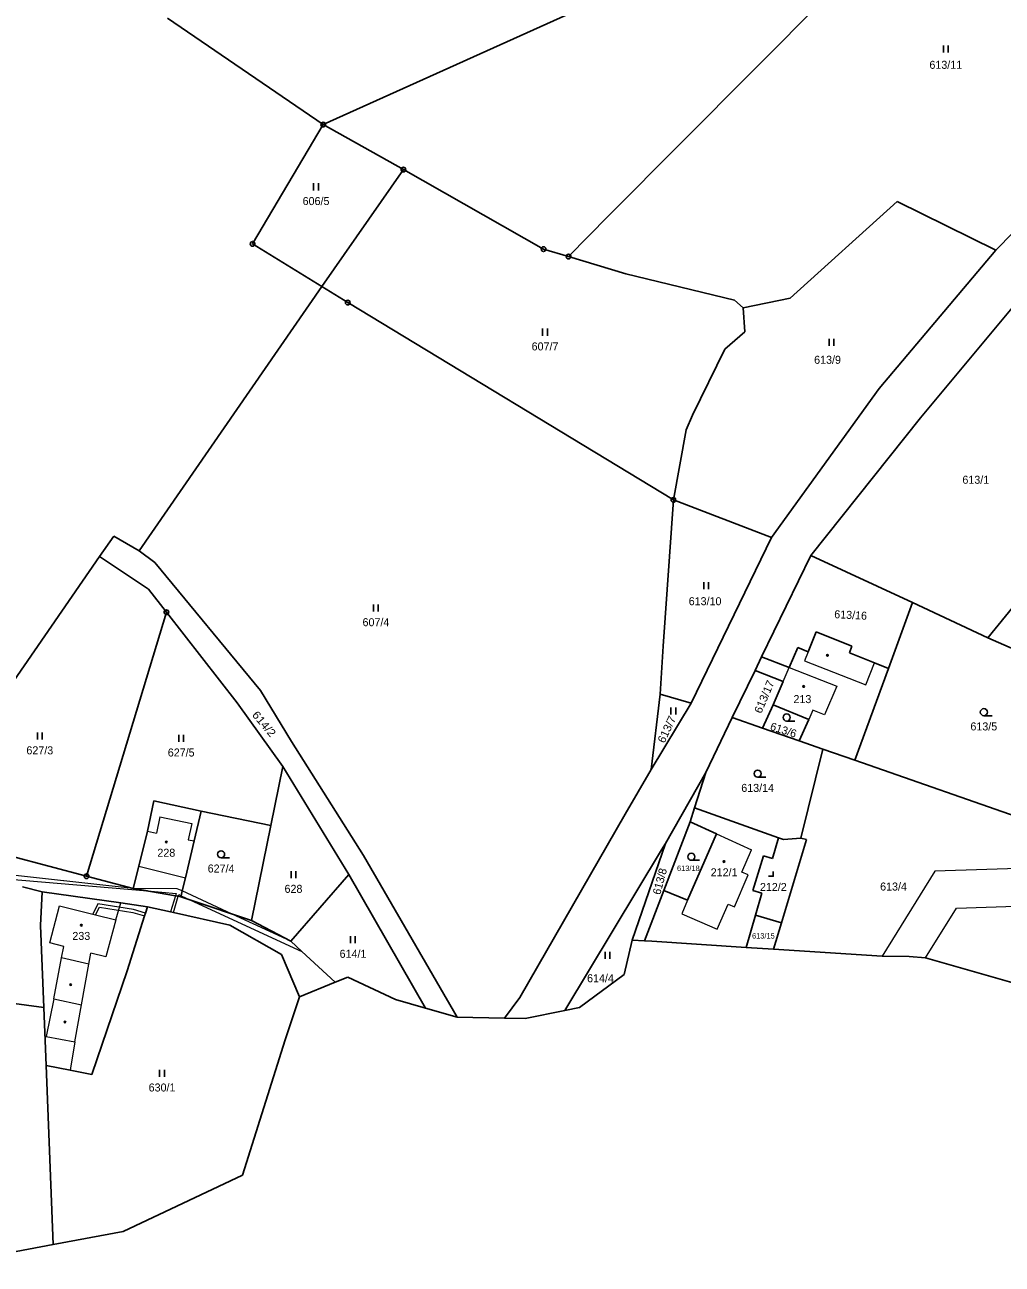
# Model space of a CAD drawing. Extents: x -739410 to -735662, y -942282 to -940043.
# Drawn here: x -737806.2 to -737598.7, y -942258.7 to -941995.4 of the extents above; entities that cross this region are included whole.
import ezdxf
from ezdxf.enums import TextEntityAlignment as Align

# ---------------------------------------------------------------- set-up
doc = ezdxf.new("R2010")
doc.units = 0
doc.header["$LTSCALE"] = 0.68
for name, color, linetype, lineweight in [('1', 7, 'Continuous', 25), ('13', 7, 'Continuous', 13), ('3', 7, 'Continuous', 25), ('4', 7, 'Continuous', 13), ('5', 7, 'Continuous', 25), ('8', 7, 'Continuous', 25)]:
    doc.layers.add(name, color=color, linetype=linetype, lineweight=lineweight)
doc.layers.add('2', color=7, linetype='Continuous')

msp = doc.modelspace()

# ---------------------------------------------------------------- linework, layer by layer
at = {"layer": '1'}
for p, q in [((-737682.23, -942036.04), (-737602.58, -941955.83)), ((-737742.81, -942016.64), (-737660.83, -941979.64)), ((-737775.89, -941994.04), (-737742.81, -942016.64)), ((-737600.02, -942043.31), (-737554.12, -941996.33)), ((-737742.81, -942016.64), (-737757.81, -942041.96)), ((-737742.81, -942016.64), (-737725.81, -942026.19)), ((-737725.81, -942026.19), (-737743.11, -942051.05)), ((-737725.81, -942026.19), (-737696.05, -942043.09)), ((-737643.66, -942053.5), (-737620.94, -942032.95)), ((-737620.94, -942032.95), (-737600.02, -942043.31)), ((-737690.74, -942044.67), (-737682.23, -942036.04)), ((-737757.81, -942041.96), (-737743.11, -942051.05)), ((-737696.05, -942043.09), (-737690.74, -942044.67)), ((-737624.79, -942072.68), (-737600.02, -942043.31)), ((-737690.74, -942044.67), (-737678.55, -942048.3)), ((-737678.55, -942048.3), (-737655.48, -942053.92)), ((-737590.28, -942048.01), (-737616.01, -942078.95)), ((-737743.11, -942051.05), (-737781.93, -942107.19)), ((-737743.11, -942051.05), (-737737.62, -942054.44)), ((-737653.69, -942055.57), (-737655.48, -942053.92)), ((-737653.69, -942055.57), (-737643.66, -942053.5)), ((-737737.62, -942054.44), (-737668.48, -942096.35)), ((-737653.31, -942060.65), (-737653.69, -942055.57)), ((-737657.57, -942064.31), (-737653.31, -942060.65)), ((-737664.41, -942078.38), (-737657.57, -942064.31)), ((-737647.63, -942104.3), (-737624.79, -942072.68)), ((-737601.7, -942125.61), (-737558.71, -942072.57)), ((-737665.79, -942081.44), (-737664.41, -942078.38)), ((-737616.01, -942078.95), (-737639.31, -942108.17)), ((-737668.48, -942096.35), (-737665.79, -942081.44)), ((-737668.48, -942096.35), (-737670.66, -942127.44)), ((-737668.48, -942096.35), (-737647.63, -942104.3)), ((-737790.3, -942108.35), (-737787.31, -942104.08)), ((-737787.31, -942104.08), (-737781.93, -942107.19)), ((-737664.73, -942139.51), (-737647.63, -942104.3)), ((-737790.3, -942108.35), (-737828.36, -942163.51)), ((-737779.93, -942115.34), (-737790.3, -942108.35)), ((-737781.93, -942107.19), (-737778.61, -942109.63)), ((-737649.74, -942129.67), (-737639.31, -942108.17)), ((-737639.31, -942108.17), (-737617.74, -942118.17)), ((-737778.61, -942109.63), (-737756.16, -942136.85)), ((-737776.12, -942120.22), (-737779.93, -942115.34)), ((-737622.84, -942132.12), (-737617.74, -942118.17)), ((-737617.74, -942118.17), (-737601.7, -942125.61)), ((-737793.06, -942176.27), (-737776.12, -942120.22)), ((-737776.12, -942120.22), (-737761.09, -942139.43)), ((-737639.86, -942128.6), (-737638.17, -942124.39)), ((-737638.17, -942124.39), (-737630.57, -942127.43)), ((-737670.66, -942127.44), (-737671.26, -942137.58)), ((-737643.92, -942131.91), (-737642.06, -942127.7)), ((-737642.06, -942127.7), (-737639.86, -942128.6)), ((-737630.57, -942127.43), (-737631.09, -942128.82)), ((-737601.7, -942125.61), (-737573.94, -942137.96)), ((-737651.15, -942132.55), (-737649.74, -942129.67)), ((-737643.92, -942131.91), (-737649.74, -942129.67)), ((-737631.09, -942128.82), (-737625.78, -942130.94)), ((-737656.03, -942142.54), (-737651.15, -942132.55)), ((-737651.15, -942132.55), (-737645.2, -942134.92)), ((-737629.96, -942151.63), (-737622.84, -942132.12)), ((-737625.78, -942130.94), (-737622.84, -942132.12)), ((-737645.2, -942134.92), (-737647.3, -942139.87)), ((-737749.53, -942147.69), (-737756.16, -942136.85)), ((-737671.26, -942137.58), (-737673.18, -942153.59)), ((-737671.26, -942137.58), (-737664.73, -942139.51)), ((-737751.4, -942152.95), (-737761.09, -942139.43)), ((-737673.18, -942153.59), (-737664.73, -942139.51)), ((-737647.3, -942139.87), (-737649.55, -942144.8)), ((-737647.3, -942139.87), (-737639.73, -942143.01)), ((-737656.03, -942142.54), (-737661.58, -942154.21)), ((-737656.03, -942142.54), (-737649.55, -942144.8)), ((-737641.75, -942147.52), (-737639.73, -942143.01)), ((-737649.55, -942144.8), (-737641.75, -942147.52)), ((-737734.24, -942171.89), (-737749.53, -942147.69)), ((-737641.75, -942147.52), (-737636.73, -942149.27)), ((-737641.41, -942168.16), (-737636.73, -942149.27)), ((-737636.73, -942149.27), (-737629.96, -942151.63)), ((-737751.4, -942152.95), (-737753.95, -942165.52)), ((-737737.37, -942175.92), (-737751.4, -942152.95)), ((-737673.18, -942153.59), (-737678.74, -942163.07)), ((-737629.96, -942151.63), (-737577.8, -942169.81)), ((-737661.58, -942154.21), (-737670.18, -942169.29)), ((-737664, -942161.77), (-737661.58, -942154.21)), ((-737778.82, -942160.24), (-737780.15, -942166.72)), ((-737768.73, -942162.43), (-737778.82, -942160.24)), ((-737664.94, -942164.69), (-737664, -942161.77)), ((-737664, -942161.77), (-737646.13, -942168.12)), ((-737770.24, -942168.79), (-737768.73, -942162.43)), ((-737768.73, -942162.43), (-737753.95, -942165.52)), ((-737701.09, -942202), (-737678.74, -942163.07)), ((-737780.15, -942166.72), (-737781.98, -942174.13)), ((-737753.95, -942165.52), (-737758.03, -942185.68)), ((-737664.94, -942164.69), (-737670.51, -942179.29)), ((-737664.94, -942164.69), (-737659.35, -942167.24)), ((-737772.1, -942176.6), (-737770.24, -942168.79)), ((-737677.2, -942189.85), (-737670.18, -942169.29)), ((-737670.18, -942169.29), (-737670.98, -942170.7)), ((-737659.35, -942167.24), (-737665.45, -942181.35)), ((-737647.46, -942172.5), (-737646.13, -942168.12)), ((-737646.13, -942168.12), (-737645.08, -942168.49)), ((-737645.54, -942186.15), (-737640.19, -942168.49)), ((-737641.41, -942168.16), (-737645.08, -942168.49)), ((-737640.19, -942168.49), (-737641.41, -942168.16)), ((-737793.06, -942176.27), (-737809.09, -942172.04)), ((-737714.39, -942206.24), (-737734.24, -942171.89)), ((-737670.98, -942170.7), (-737691.53, -942204.77)), ((-737651.61, -942179.29), (-737649.37, -942171.92)), ((-737649.37, -942171.92), (-737647.46, -942172.5)), ((-737781.98, -942174.13), (-737783.15, -942178.88)), ((-737793.06, -942176.27), (-737783.15, -942178.88)), ((-737749.72, -942190.07), (-737737.37, -942175.92)), ((-737737.37, -942175.92), (-737721.1, -942204.3)), ((-737806.64, -942178.51), (-737802.49, -942179.57)), ((-737802.49, -942179.57), (-737802.84, -942186.71)), ((-737785.81, -942181.94), (-737802.49, -942179.57)), ((-737670.51, -942179.29), (-737674.6, -942190)), ((-737665.45, -942181.35), (-737670.51, -942179.29)), ((-737649.69, -942179.87), (-737651.61, -942179.29)), ((-737651.06, -942184.55), (-737649.69, -942179.87)), ((-737780.15, -942182.74), (-737785.81, -942181.94)), ((-737653.05, -942191.38), (-737651.06, -942184.55)), ((-737645.54, -942186.15), (-737651.06, -942184.55)), ((-737802.84, -942186.71), (-737802.11, -942204.16)), ((-737751.69, -942192.88), (-737762.68, -942186.7)), ((-737758.03, -942185.68), (-737749.72, -942190.07)), ((-737647.24, -942191.75), (-737645.54, -942186.15)), ((-737673.08, -942190.09), (-737674.6, -942190)), ((-737747.87, -942201.88), (-737751.69, -942192.88)), ((-737647.24, -942191.75), (-737624.15, -942193.23)), ((-737618.39, -942193.32), (-737624.15, -942193.23)), ((-737614.97, -942193.62), (-737618.39, -942193.32)), ((-737614.97, -942193.62), (-737583.13, -942202.66)), ((-737784.47, -942196.37), (-737791.97, -942218.37)), ((-737737.62, -942197.69), (-737740.31, -942198.79)), ((-737737.62, -942197.69), (-737727.48, -942202.46)), ((-737678.94, -942197.16), (-737688.43, -942204.14)), ((-737802.11, -942204.16), (-737825.45, -942200.97)), ((-737740.31, -942198.79), (-737747.87, -942201.88)), ((-737747.87, -942201.88), (-737750.89, -942211)), ((-737727.48, -942202.46), (-737721.1, -942204.3)), ((-737701.09, -942202), (-737704.32, -942206.41)), ((-737801.68, -942216.45), (-737802.11, -942204.16)), ((-737721.1, -942204.3), (-737714.39, -942206.24)), ((-737704.32, -942206.41), (-737714.39, -942206.24)), ((-737699.98, -942206.49), (-737704.32, -942206.41)), ((-737691.53, -942204.77), (-737699.98, -942206.49)), ((-737688.43, -942204.14), (-737691.53, -942204.77)), ((-737750.89, -942211), (-737759.97, -942239.78)), ((-737791.97, -942218.37), (-737796.57, -942217.46)), ((-737759.97, -942239.78), (-737785.29, -942251.72))]:
    msp.add_line(p, q, dxfattribs=at)
for points in [[(-737773.06, -942180.63), (-737773.01, -942180.41), (-737772.77, -942179.41), (-737772.1, -942176.6)], [(-737783.15, -942178.88), (-737774.19, -942180.43), (-737773.59, -942180.54), (-737773.06, -942180.63)], [(-737780.15, -942182.74), (-737780.59, -942184.13), (-737780.77, -942184.7), (-737784.47, -942196.37)], [(-737762.68, -942186.7), (-737774.63, -942183.99), (-737775.22, -942183.86), (-737780.15, -942182.74)], [(-737773.06, -942180.63), (-737771.12, -942181.28), (-737758.03, -942185.68)], [(-737740.31, -942198.79), (-737747.33, -942192.29), (-737749.72, -942190.07)], [(-737674.6, -942190), (-737677.2, -942189.85), (-737678.94, -942197.16)], [(-737673.08, -942190.09), (-737653.05, -942191.38), (-737647.24, -942191.75)], [(-737796.57, -942217.46), (-737801.68, -942216.45), (-737800.14, -942254.51)], [(-737785.29, -942251.72), (-737800.14, -942254.51), (-737822.32, -942258.68)]]:
    msp.add_lwpolyline(points, dxfattribs=at)
at = {"layer": '13'}
for points in [[(-737579.87, -942174.12), (-737612.94, -942175.17), (-737624.15, -942193.23), (-737618.39, -942193.32), (-737614.97, -942193.62), (-737608.4, -942183.03), (-737581.06, -942182.16), (-737577.8, -942169.81)], [(-737780.15, -942179.4), (-737783.15, -942178.88), (-737812.79, -942175.62), (-737819.06, -942175.09), (-737818.22, -942175.34), (-737813.83, -942176.54), (-737810.17, -942176.85)], [(-737762.13, -942184.3), (-737772.77, -942179.41), (-737773.8, -942178.94), (-737783.15, -942178.88), (-737780.15, -942179.4), (-737774.03, -942179.92), (-737774.19, -942180.43), (-737773.59, -942180.54), (-737773.48, -942180.19), (-737773.01, -942180.41), (-737771.12, -942181.28)], [(-737780.59, -942184.13), (-737783.14, -942183.37), (-737790.65, -942182.17), (-737791.77, -942184.35), (-737791.18, -942184.5), (-737790.31, -942182.83), (-737783.28, -942183.95), (-737780.77, -942184.7)], [(-737774.63, -942183.99), (-737773.59, -942180.54), (-737774.19, -942180.43), (-737775.22, -942183.86)], [(-737747.33, -942192.29), (-737749.72, -942190.07), (-737762.13, -942184.3), (-737771.12, -942181.28)]]:
    msp.add_lwpolyline(points, close=True, dxfattribs=at)
at = {"layer": '3'}
for p, q in [((-737611.161, -942001.3), (-737611.161, -941999.8)), ((-737610.16, -942001.3), (-737610.16, -941999.8)), ((-737744.861, -942030.6), (-737744.861, -942029.1)), ((-737743.86, -942030.6), (-737743.86, -942029.1)), ((-737696.241, -942061.47), (-737696.241, -942059.97)), ((-737695.24, -942061.47), (-737695.24, -942059.97)), ((-737635.411, -942063.62), (-737635.411, -942062.12)), ((-737634.41, -942063.62), (-737634.41, -942062.12)), ((-737662.031, -942115.32), (-737662.031, -942113.82)), ((-737661.03, -942115.32), (-737661.03, -942113.82)), ((-737732.141, -942120.05), (-737732.141, -942118.55)), ((-737731.14, -942120.05), (-737731.14, -942118.55)), ((-737668.991, -942141.93), (-737668.991, -942140.43)), ((-737667.99, -942141.93), (-737667.99, -942140.43)), ((-737644.433, -942143.31), (-737642.683, -942143.31)), ((-737602.563, -942142.18), (-737600.813, -942142.18)), ((-737803.511, -942147.26), (-737803.511, -942145.76)), ((-737802.51, -942147.26), (-737802.51, -942145.76)), ((-737773.491, -942147.72), (-737773.491, -942146.22)), ((-737772.49, -942147.72), (-737772.49, -942146.22)), ((-737650.583, -942155.24), (-737648.833, -942155.24)), ((-737764.503, -942172.36), (-737762.753, -942172.36)), ((-737664.673, -942172.89), (-737662.923, -942172.89)), ((-737749.651, -942176.68), (-737749.651, -942175.18)), ((-737748.65, -942176.68), (-737748.65, -942175.18)), ((-737737.011, -942190.48), (-737737.011, -942188.98)), ((-737736.01, -942190.48), (-737736.01, -942188.98)), ((-737682.951, -942193.85), (-737682.951, -942192.35)), ((-737681.95, -942193.85), (-737681.95, -942192.35)), ((-737777.551, -942218.87), (-737777.551, -942217.37)), ((-737776.55, -942218.87), (-737776.55, -942217.37))]:
    msp.add_line(p, q, dxfattribs=at)
msp.add_lwpolyline([(-737648.261, -942176.28), (-737647.26, -942176.28), (-737647.26, -942175.28)], dxfattribs=at)
for centre in [(-737602.5629, -942141.4298), (-737644.4329, -942142.5598), (-737650.5829, -942154.4898), (-737764.5029, -942171.6098), (-737664.6729, -942172.1398)]:
    msp.add_circle(centre, 0.75, dxfattribs=at)
at = {"layer": '4'}
for p, q in [((-737645.2, -942134.92), (-737643.92, -942131.91)), ((-737643.92, -942131.91), (-737633.8, -942135.94)), ((-737627.64, -942135.59), (-737625.78, -942130.94)), ((-737632.85, -942133.56), (-737627.64, -942135.59)), ((-737633.8, -942135.94), (-737636.38, -942142)), ((-737777.49, -942163.66), (-737778.24, -942167.12)), ((-737777.49, -942163.66), (-737770.73, -942165.07)), ((-737780.15, -942166.72), (-737778.24, -942167.12)), ((-737770.73, -942165.07), (-737771.48, -942168.53)), ((-737771.48, -942168.53), (-737770.24, -942168.79)), ((-737659.35, -942167.24), (-737651.89, -942170.64)), ((-737653.95, -942175.41), (-737651.89, -942170.64)), ((-737781.98, -942174.13), (-737772.1, -942176.6)), ((-737655.5, -942182.79), (-737652.57, -942176)), ((-737652.57, -942176), (-737653.95, -942175.41)), ((-737798.85, -942182.53), (-737791.77, -942184.35)), ((-737786.85, -942185.56), (-737785.81, -942181.94)), ((-737665.45, -942181.35), (-737666.71, -942184.27)), ((-737659.18, -942187.52), (-737656.88, -942182.2)), ((-737656.88, -942182.2), (-737655.5, -942182.79)), ((-737791.77, -942184.35), (-737791.18, -942184.5)), ((-737791.18, -942184.5), (-737786.85, -942185.56)), ((-737786.85, -942185.56), (-737788.97, -942193.43)), ((-737666.71, -942184.27), (-737659.18, -942187.52)), ((-737798.36, -942193.6), (-737797.89, -942191.18)), ((-737792.59, -942194.97), (-737792.13, -942192.63)), ((-737788.97, -942193.43), (-737792.13, -942192.63)), ((-737800.04, -942202.29), (-737798.36, -942193.6)), ((-737792.59, -942194.97), (-737798.36, -942193.6)), ((-737794.13, -942203.57), (-737792.59, -942194.97)), ((-737800.04, -942202.29), (-737801.68, -942210.29)), ((-737800.04, -942202.29), (-737794.13, -942203.57)), ((-737795.55, -942211.45), (-737794.13, -942203.57)), ((-737801.68, -942210.29), (-737795.55, -942211.45)), ((-737795.55, -942211.45), (-737796.57, -942217.46))]:
    msp.add_line(p, q, dxfattribs=at)
for points in [[(-737639.86, -942128.6), (-737640.63, -942130.53), (-737632.85, -942133.56)], [(-737636.38, -942142), (-737638.84, -942141), (-737639.73, -942143.01)], [(-737797.89, -942191.18), (-737800.9, -942190.42), (-737798.85, -942182.53)]]:
    msp.add_lwpolyline(points, dxfattribs=at)
at = {"layer": '5'}
for centre in [(-737635.7668, -942129.3592), (-737640.8068, -942135.9692), (-737776.1468, -942169.0092), (-737657.7168, -942173.1592), (-737794.1968, -942186.6792), (-737796.4568, -942199.2992), (-737797.6468, -942207.2392)]:
    msp.add_circle(centre, 0.175, dxfattribs=at)
at = {"layer": '8'}
for centre, radius in [((-737742.81, -942016.6399), 0.5), ((-737742.81, -942016.6399), 0.0303), ((-737725.81, -942026.1899), 0.5), ((-737725.81, -942026.1899), 0.0303), ((-737757.81, -942041.9599), 0.5), ((-737757.81, -942041.9599), 0.0303), ((-737696.05, -942043.0899), 0.5), ((-737696.05, -942043.0899), 0.0303), ((-737690.74, -942044.6699), 0.5), ((-737690.74, -942044.6699), 0.0303), ((-737737.62, -942054.4399), 0.5), ((-737737.62, -942054.4399), 0.0303), ((-737668.48, -942096.3499), 0.5), ((-737668.48, -942096.3499), 0.0303), ((-737776.12, -942120.2199), 0.5), ((-737776.12, -942120.2199), 0.0303), ((-737793.06, -942176.2699), 0.5), ((-737793.06, -942176.2699), 0.0303)]:
    msp.add_circle(centre, radius, dxfattribs=at)

# ---------------------------------------------------------------- texts
at = {"layer": '2'}
for s, height, p in [('613/11', 1.7, (-737610.64, -942004.785)), ('606/5', 1.7, (-737744.35, -942033.725)), ('607/7', 1.7, (-737695.73, -942064.595)), ('613/9', 1.7, (-737635.75, -942067.435)), ('613/1', 1.7, (-737604.27, -942092.915)), ('613/10', 1.7, (-737661.75, -942118.715)), ('607/4', 1.7, (-737731.63, -942123.175)), ('213', 1.7, (-737641.089, -942139.505)), ('613/5', 1.7, (-737602.57, -942145.305)), ('627/3', 1.7, (-737803, -942150.385)), ('627/5', 1.7, (-737772.98, -942150.845)), ('613/14', 1.7, (-737650.59, -942158.365)), ('228', 1.7, (-737776.139, -942172.135)), ('627/4', 1.7, (-737764.51, -942175.485)), ('613/18', 1.14, (-737665.299, -942175.165)), ('212/1', 1.7, (-737657.71, -942176.285)), ('212/2', 1.7, (-737647.26, -942179.405)), ('613/4', 1.7, (-737621.74, -942179.315)), ('628', 1.7, (-737749.139, -942179.805)), ('233', 1.7, (-737794.189, -942189.805)), ('613/15', 1.14, (-737649.369, -942189.505)), ('614/1', 1.7, (-737736.5, -942193.605)), ('614/4', 1.7, (-737683.96, -942198.795)), ('630/1', 1.7, (-737777.04, -942221.995))]:
    msp.add_text(s, height=height, dxfattribs=at).set_placement(p, align=Align.CENTER)
for s, rotation, p in [('613/16', 357, (-737630.8885, -942121.6346)), ('613/6', 342, (-737645.3767, -942146.027)), ('613/8', 75, (-737670.5391, -942177.588))]:
    msp.add_text(s, height=1.7, rotation=rotation, dxfattribs=at).set_placement(p, align=Align.CENTER)
for s, rotation, width, p in [('613/17', 67, 1.05, (-737648.4068, -942138.4961)), ('614/2', 310, 1.1, (-737756.0317, -942144.4706)), ('613/7', 65, 1.05, (-737669.1191, -942145.4457))]:
    msp.add_text(s, height=1.7, rotation=rotation, dxfattribs=dict(at, width=width)).set_placement(p, align=Align.CENTER)

doc.saveas('drawing.dxf')
